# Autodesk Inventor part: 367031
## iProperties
Created: 2006-08
Part Number: 367031
Material: 10.9 vz
Description: Senkschraube
Vendor: Autodesk Inc.
Document SubType Name: Modeling
Standard: DIN 7991
Designer: I.Baliuc
Standards Organization: DIN
Language: de-DE
Size Designation: M8 x 25
Categories: <MemberInstance Version="R10.0.0"><Categories><Category DisplayName="Schrauben" InternalName="e4da775c-781d-43d5-af7c-5136215cf5a6" Mnemonic="FSTN"><Category Di
Density: 7.85 g/cm^3
Abmessung: M8 x 25
Author: T.Messerschmitt
Comments: DIN 7991 - M8 x 25
Revision Number: 367031
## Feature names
1. Körper [Revolution]
2. Loch [Extrusion]
3. Fase1 [Chamfer]
